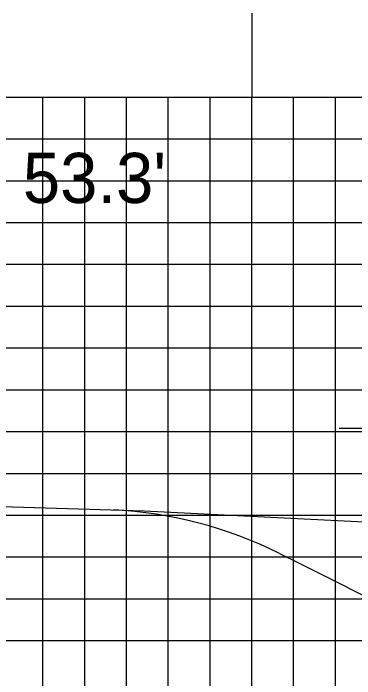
# Model space of a CAD drawing. Extents: x 1773203 to 1773546, y 442591 to 442811.
# Drawn here: x 1773312.93 to 1773321.09, y 442614.75 to 442630.67 of the extents above; entities that cross this region are included whole.
import ezdxf

# ---------------------------------------------------------------- set-up
doc = ezdxf.new("R2010")
doc.units = 0
for name, color, linetype in [('ANNOTATION', 7, 'Continuous'), ('D_Roadway_SlopeLines', 7, 'Continuous'), ('D_Text_Standard', 7, 'Continuous'), ('MAJOR', 7, 'Continuous'), ('MINOR', 7, 'Continuous'), ('S_Roadway_Centerline', 7, 'Continuous')]:
    doc.layers.add(name, color=color, linetype=linetype)

msp = doc.modelspace()

# ---------------------------------------------------------------- linework, layer by layer
at = {"layer": 'ANNOTATION'}
msp.add_lwpolyline([(1773320.724, 442620.744), (1773326.416, 442620.744), (1773328.84, 442616.34)], dxfattribs=at)
at = {"layer": 'D_Roadway_SlopeLines'}
msp.add_line((1773319.294, 442617.748), (1773319.747, 442617.522), dxfattribs=at)
msp.add_lwpolyline([(1773319.747, 442617.522), (1773322.09, 442616.35), (1773324.09, 442616.347), (1773324.326, 442616.347)], dxfattribs=at)
msp.add_arc((1773314.822, 442608.804), 10, 63.4349, 87.1433, dxfattribs=at)
at = {"layer": 'MAJOR'}
for p, q in [((1773318.633, 442630.669), (1773318.633, 442628.665)), ((1773228.633, 442628.665), (1773508.633, 442628.665)), ((1773228.633, 442628.665), (1773508.633, 442628.665)), ((1773318.633, 442608.665), (1773318.633, 442628.665)), ((1773228.633, 442623.665), (1773508.633, 442623.665)), ((1773228.633, 442618.665), (1773508.633, 442618.665))]:
    msp.add_line(p, q, dxfattribs=at)
at = {"layer": 'MINOR'}
for p, q in [((1773313.633, 442608.665), (1773313.633, 442628.665)), ((1773314.633, 442608.665), (1773314.633, 442628.665)), ((1773315.633, 442608.665), (1773315.633, 442628.665)), ((1773316.633, 442608.665), (1773316.633, 442628.665)), ((1773317.633, 442608.665), (1773317.633, 442628.665)), ((1773319.633, 442608.665), (1773319.633, 442628.665)), ((1773320.633, 442608.665), (1773320.633, 442628.665)), ((1773228.633, 442627.665), (1773508.633, 442627.665)), ((1773228.633, 442626.665), (1773508.633, 442626.665)), ((1773228.633, 442625.665), (1773508.633, 442625.665)), ((1773228.633, 442624.665), (1773508.633, 442624.665)), ((1773228.633, 442622.665), (1773508.633, 442622.665)), ((1773228.633, 442621.665), (1773508.633, 442621.665)), ((1773228.633, 442620.665), (1773508.633, 442620.665)), ((1773228.633, 442619.665), (1773508.633, 442619.665)), ((1773228.633, 442617.665), (1773508.633, 442617.665)), ((1773228.633, 442616.665), (1773508.633, 442616.665)), ((1773228.633, 442615.665), (1773508.633, 442615.665))]:
    msp.add_line(p, q, dxfattribs=at)
at = {"layer": 'S_Roadway_Centerline'}
msp.add_lwpolyline([(1773304.246, 442619.123), (1773316.056, 442618.769), (1773325.791, 442618.283), (1773327.822, 442618.218), (1773329.759, 442618.149), (1773347.396, 442617.953), (1773350.966, 442617.999), (1773356.015, 442617.783), (1773363.1, 442617.486), (1773368.852, 442617.324), (1773375.69, 442617.133), (1773386.091, 442616.801), (1773391.839, 442616.688), (1773407.669, 442616.423), (1773417.972, 442616.208), (1773429.278, 442615.936)], dxfattribs=at)

# ---------------------------------------------------------------- texts
at = {"layer": 'D_Text_Standard'}
msp.add_text("53.3'", height=1.2, dxfattribs=at).set_placement((1773313.153, 442626.132))

doc.saveas('drawing.dxf')
